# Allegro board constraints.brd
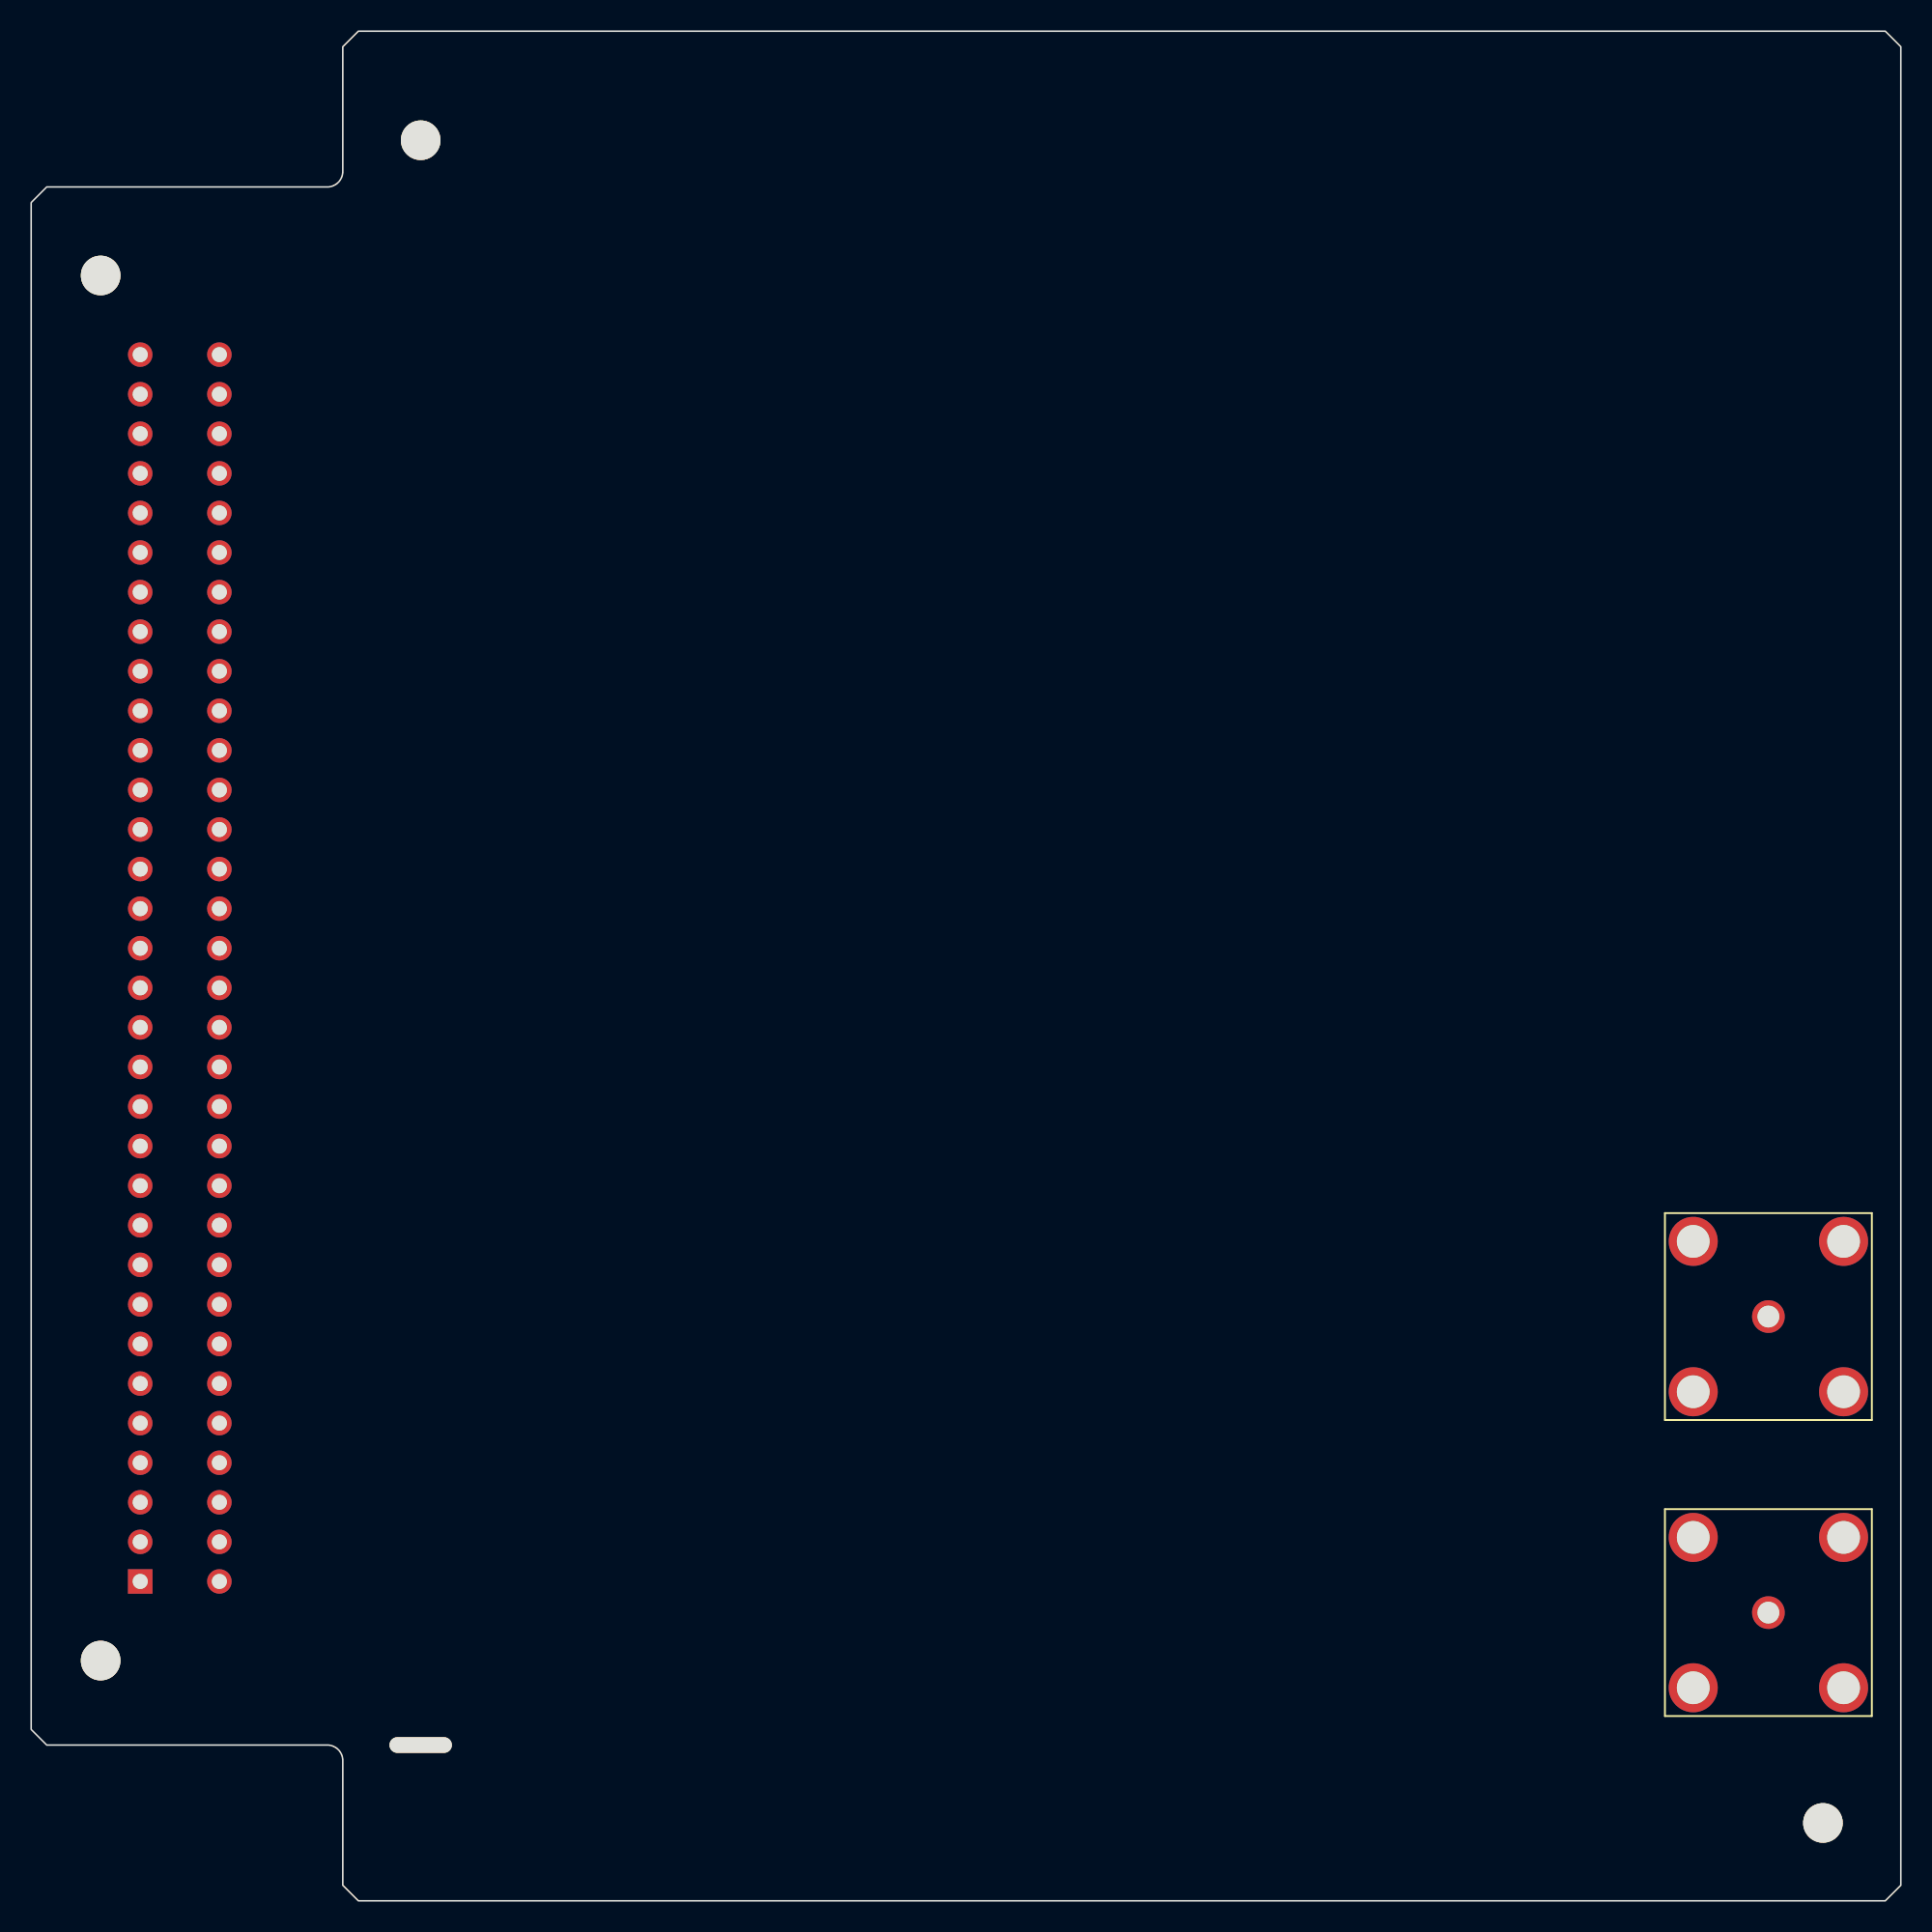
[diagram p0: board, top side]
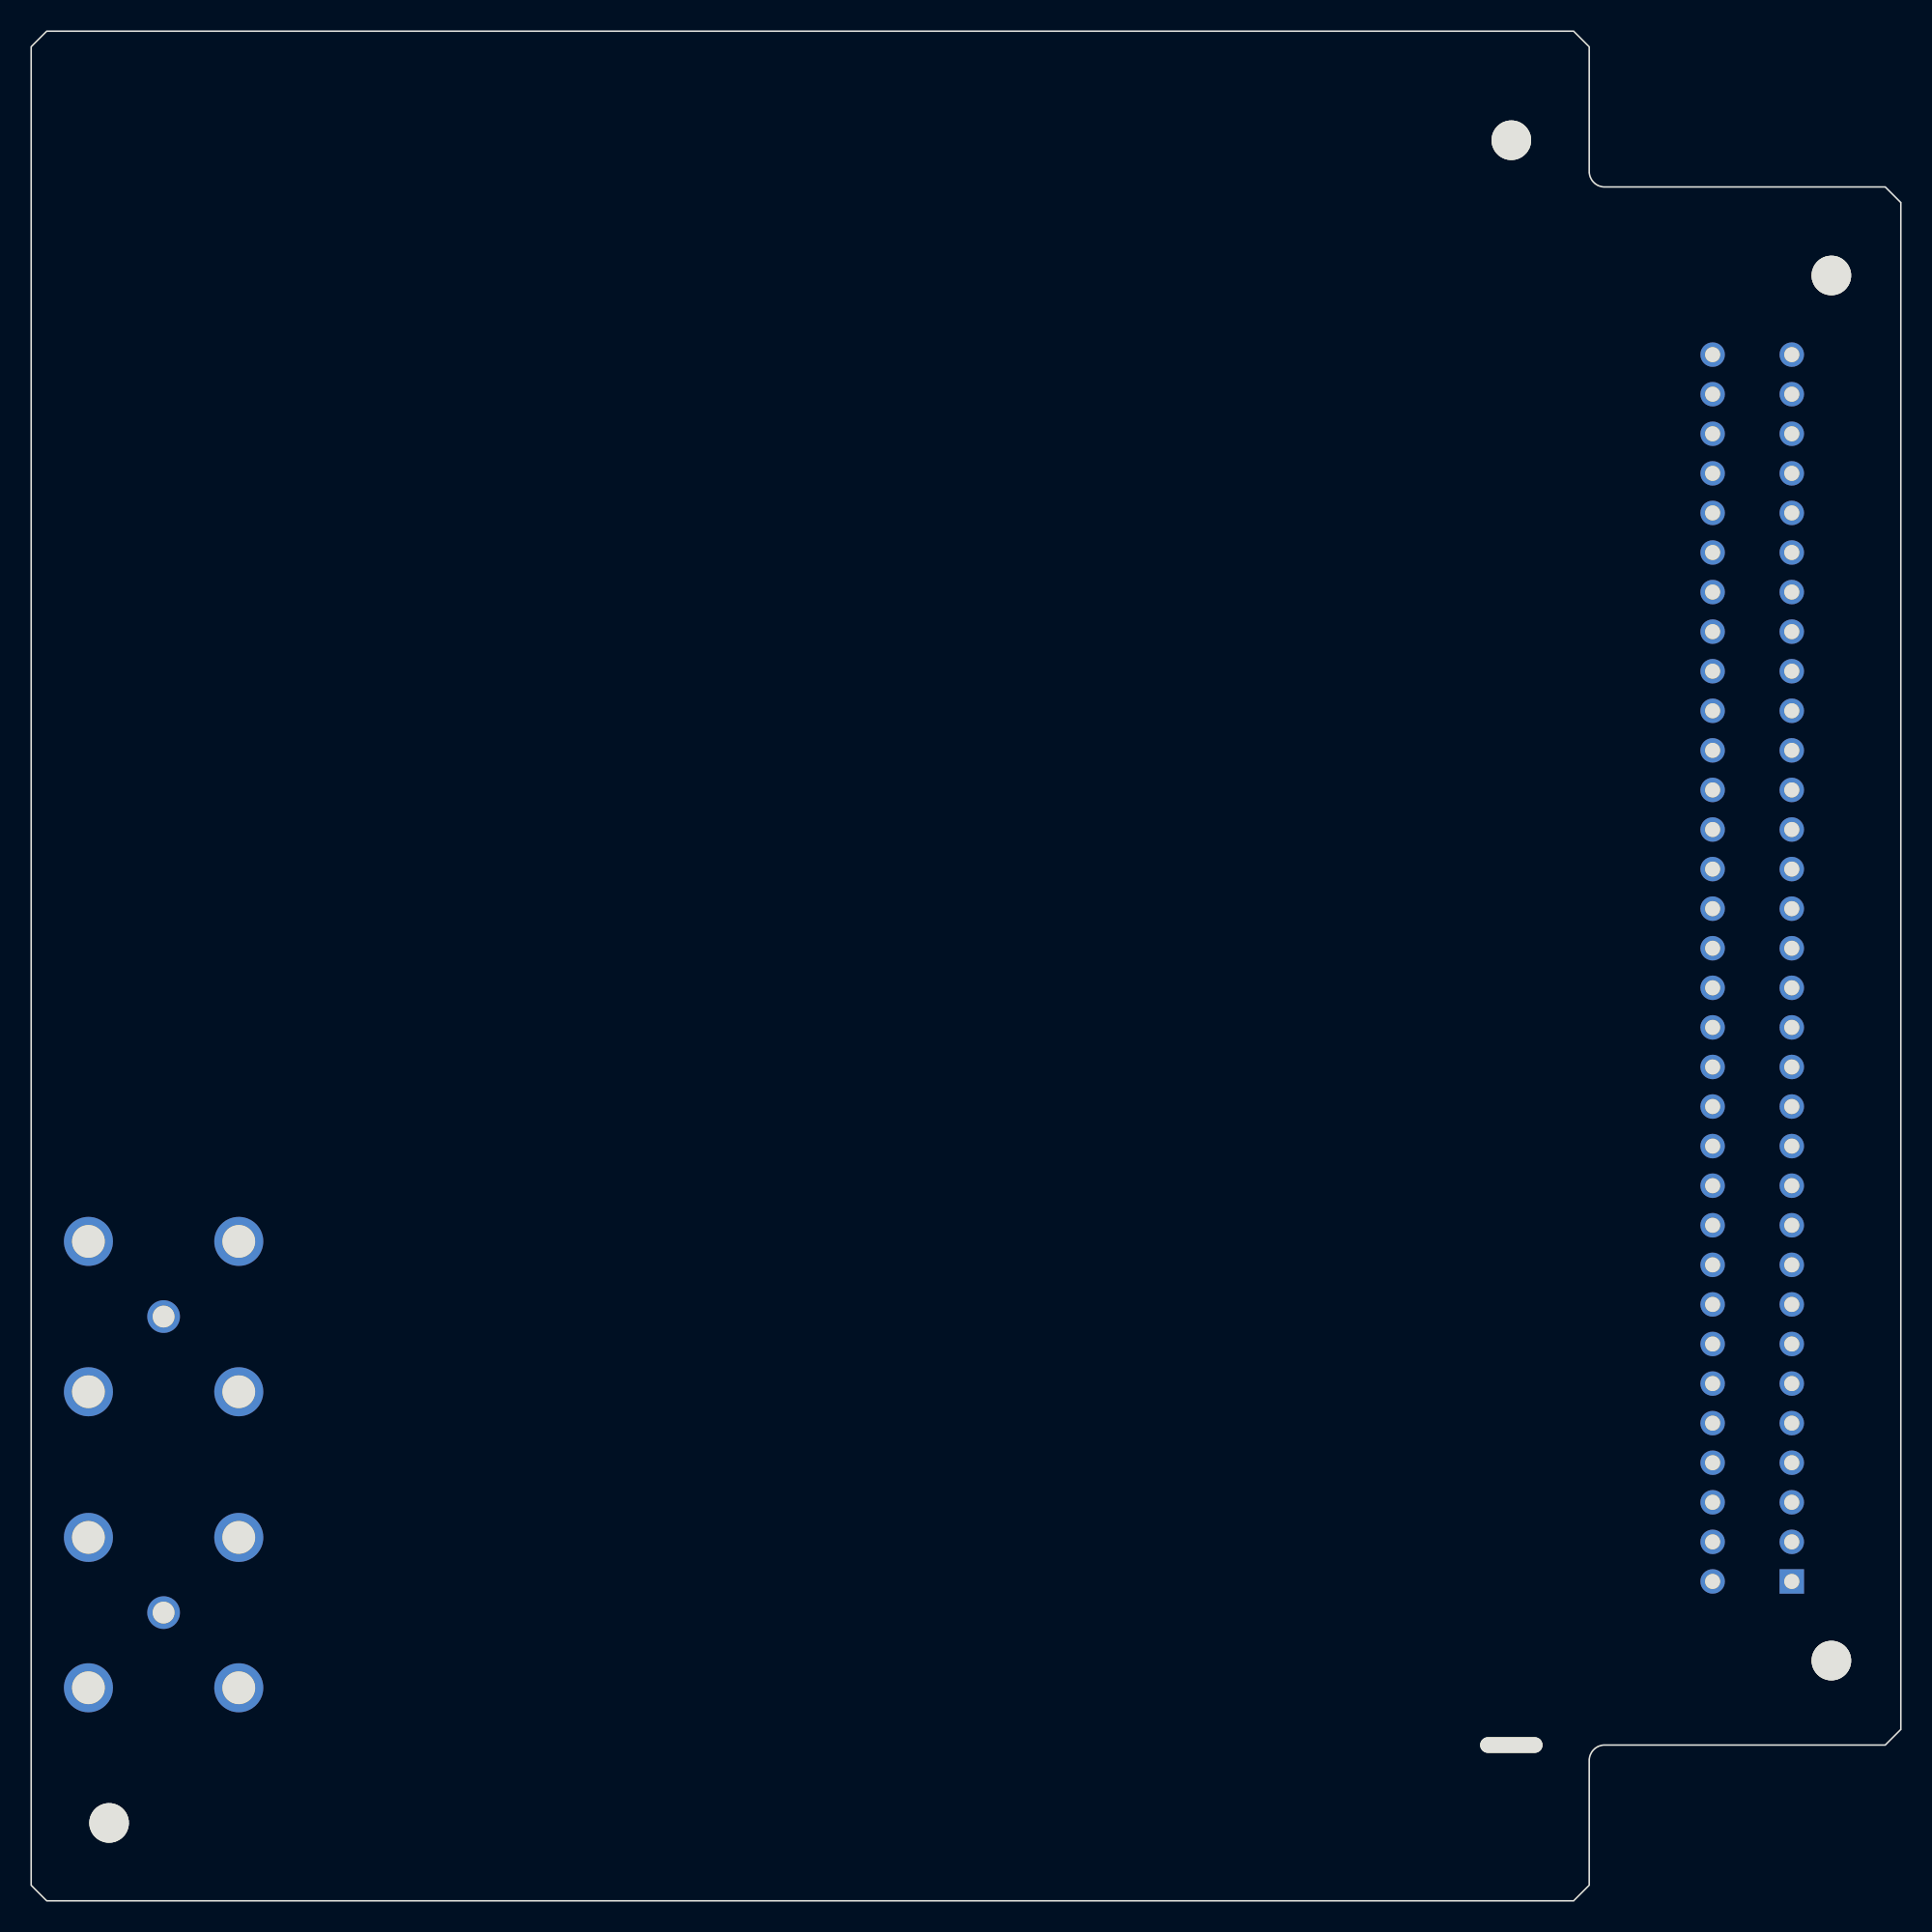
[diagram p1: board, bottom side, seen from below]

Outline 120 x 120 mm; copper layers: TOP, GND1, VCC1, VCC2, GND2, BOTTOM. Coordinates in mm from the lower left corner of the outline.

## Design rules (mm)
constraint set DEFAULT: min track width 0.15
net group SYNC: nets VCLKA VCLKC
net group MEMORY[0..28]: nets MEMORY.RA0 MEMORY.RA1 MEMORY.RA2 MEMORY.RA3 MEMORY.RA4 MEMORY.RA5 MEMORY.RA6 MEMORY.RA7 MEMORY.RA8 MEMORY.RA9 MEMORY.RA10 MEMORY.RA11 MEMORY.RA12 MEMORY.RA13 MEMORY.RA14 MEMORY.RA15 MEMORY.RCS0 MEMORY.RCS1 MEMORY.RCS2 MEMORY.RCS3 MEMORY.RD0 MEMORY.RD1 MEMORY.RD2 MEMORY.RD3 MEMORY.RD4 MEMORY.RD5 MEMORY.RD6 MEMORY.RD7 MEMORY.RWE
net group POWER: nets AGND GND_EARTH V12N V+12
net group VDNETS: nets VD0 VD1 VD2 VD3 VD4 VD5 VD6 VD7
nets with their own width: min track width 0.4; nets GND VCC

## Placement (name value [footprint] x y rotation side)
J1  CON64  [DIN64]  7 20.5 0 top
J2  BNC  [CONNEX_112659]  111.5 37.5 0 top
J3  BNC  [CONNEX_112659]  111.5 18.5 0 top
NOREF  -  []  0 15.3 0 top
NOREF#2  -  []  25.27 0 90 top
NOREF#3  -  []  25 10 90 top
NOREF#4  -  []  119.43 119.57 0 top
NOREF#5  -  []  25 10 0 top
NOREF#6  -  []  197.72 152.24 0 top
NOREF#7  -  []  20 4.47 0 top
NOREF#8  -  []  -71.52 -89.06 0 top
NOREF#9  -  [unnamed#2]  25 10 0 top
NOREF#10  -  []  25 10 0 top
NOREF#11  -  []  25 10 90 top
NOREF#12  -  []  19.76 110.35 0 top
NOREF#13  -  []  25 10 90 top

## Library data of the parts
J1 = CON64
J2 = BNC: room: CHAN1
J3 = BNC: room: CHAN2

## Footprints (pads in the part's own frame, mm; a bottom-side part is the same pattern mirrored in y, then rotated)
CONNEX_112659
  round 2.1 hole 1.4: 1(0,0)
  round 3.15 hole 2.1: 2(-4.825,4.825) 3(4.825,4.825) 4(4.825,-4.825) 5(-4.825,-4.825)
DIN64
  round 2.54 hole 2.794 unplated: (-2.54,83.82) (-2.54,-5.08)
  rect 1.575x1.575 hole 0.965: 1(0,0)
  round 1.575 hole 0.965: 2(0,2.54) 3(0,5.08) 4(0,7.62) 5(0,10.16) 6(0,12.7) 7(0,15.24) 8(0,17.78) 9(0,20.32) 10(0,22.86) 11(0,25.4) 12(0,27.94) 13(0,30.48) 14(0,33.02) 15(0,35.56) 16(0,38.1) 17(0,40.64) 18(0,43.18) 19(0,45.72) 20(0,48.26) 21(0,50.8) 22(0,53.34) 23(0,55.88) 24(0,58.42) 25(0,60.96) 26(0,63.5) 27(0,66.04) 28(0,68.58) 29(0,71.12) 30(0,73.66) 31(0,76.2) 32(0,78.74) 33(5.08,0) 34(5.08,2.54) 35(5.08,5.08) 36(5.08,7.62) 37(5.08,10.16) 38(5.08,12.7) 39(5.08,15.24) 40(5.08,17.78) 41(5.08,20.32) 42(5.08,22.86) 43(5.08,25.4) 44(5.08,27.94) 45(5.08,30.48) 46(5.08,33.02) 47(5.08,35.56) 48(5.08,38.1) 49(5.08,40.64) 50(5.08,43.18) 51(5.08,45.72) 52(5.08,48.26) 53(5.08,50.8) 54(5.08,53.34) 55(5.08,55.88) 56(5.08,58.42) 57(5.08,60.96) 58(5.08,63.5) 59(5.08,66.04) 60(5.08,68.58) 61(5.08,71.12) 62(5.08,73.66) 63(5.08,76.2) 64(5.08,78.74)
unnamed#2
  round 2.54 hole 2.794 unplated: (0,103) (90,-5)
  oval 4x1 hole 5x1.5 unplated: (0,0)

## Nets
AGND: J1.34 J1.35 J1.36
GND: J1.1 J1.2 J1.3 J1.33
GND_EARTH: J2.2 J2.3 J2.4 J2.5(GND5) J3.2 J3.3 J3.4 J3.5(GND5)
V12N: J1.31 J1.32
VCC: J1.29 J1.30 J1.62
A0: J1.54
A1: J1.55
A2: J1.56
A3: J1.57
A4: J1.58
A5: J1.59
A6: J1.60
A7: J1.61
A8: J1.13
A9: J1.14
A10: J1.15
A11: J1.16
A12: J1.17
A13: J1.18
A14: J1.19
A15: J1.20
A16: J1.37
A17: J1.38
A18: J1.39
A19: J1.40
A20: J1.41
A21: J1.42
A22: J1.43
A23: J1.44
AEN: J1.47
BNC2: J2.1
BNC3: J3.1
D0: J1.28
D1: J1.27
D2: J1.26
D3: J1.25
D4: J1.24
D5: J1.23
D6: J1.22
D7: J1.21
D8: J1.4
D9: J1.5
D10: J1.6
D11: J1.7
D12: J1.8
D13: J1.9
D14: J1.10
D15: J1.11
MCLK: J1.52
MRD: J1.46
MWR: J1.45
RDY: J1.50
RESET: J1.53
V+12: J1.63 J1.64
WAIT: J1.51

Pads without a net: J1 12 48 49
